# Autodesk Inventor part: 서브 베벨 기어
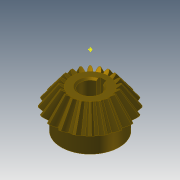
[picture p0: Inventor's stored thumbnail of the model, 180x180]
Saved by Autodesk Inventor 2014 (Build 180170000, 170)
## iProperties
Created: 2014-10
Part Number: 서브 베벨 기어
Material: Steel, Mild
Document SubType Name: Modeling
Designer: KYOUNG IL JANG
Categories: <?xml version="1.0" encoding="UTF-16"?> <MemberInstance><Categories><FamilyTemplate><FamilyTemplateParameter ValueType="xs:double" Id="1" ObjectReferenceKey="da
Mass: 134.866 g
Surface Area: 63.6518 cm^2
Volume: 17.1585 cm^3
Density: 7.86 g/cm^3
Appearance: 얼룩무늬
CustomPartVersion: 1
Company: 한국ATC센터
Author: KYOUNG IL JANG
Revision Number: 1
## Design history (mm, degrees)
node "맨 위 점"
node "메쉬 평면2"
sketch "톱니 본체 스케치"
  geometry: L1 (0, 0)-(18.003, -31.331); L2 (18.003, -31.331)-(21.664, -28.891); L3 (21.664, -28.891)-(0, 0); L4 (20, -30)-(0, 0); L5 (10.813, -18.818)-(13.012, -17.352); L6 (18.003, -31.331)-(10.813, -18.818); L7 (21.664, -28.891)-(13.012, -17.352); L8 (0, -39.387)-(0, 6.564) reference; L9 (0, -30)-(21.664, -30)
  constraints: 16 end point, 4 point on line, 3 perpendicular, 2 collinear, 1 horizontal alignment, 1 vertical alignment
  dimensions: "d0" = 40 diameter of L4.start L8 (= da_de); "d1" = 36.00616 diameter of L1.end L8 (= da_dfe); "d2" = 43.3282 diameter of L2.end L8 (= da_dae); "d3" = 14.4 distance between parallel lines of L2 L5 (= da_b); "d4" = 28.8906 vertical distance of L2.end L1.start (= da_ve)
revolve "톱니 본체" sketch "톱니 본체 스케치" stored, may be unused: angle "d5" = 90 deg
node "시작점"
node "톱니 평면"
sketch "시작 스케치"
  geometry: L1 (0, -23.505)-(0, 10.645) reference; L2 (-0.834, -2.928)-(0.834, -2.928); A1 r 8.898 centre (-9.698, -3.713) between (-0.834, -2.928) and (-3.903, 3.04); A2 r 8.898 centre (9.698, -3.713) between (3.903, 3.04) and (0.834, -2.928); A3 r 27.357 centre (0, -24.037) between (3.903, 3.04) and (-3.903, 3.04); 1 further point
  constraints: 6 point on circle, 3 centre point, 3 symmetric about line, 2 end point, 1 coincident, 1 perpendicular, 1 other
  dimensions: "d7" = 8.89846 radius of A1 (= fd_rr); "d8" = 9.69794 horizontal distance of point (0, -24.037) A1.centre (= fd_x); "d9" = 20.32439 vertical distance of point (0, -24.037) A1.centre (= fd_y); "d57" = 27.35701 radius of A3 (= 0.5 x fd_dva + 0.3 x da_he); "d58" = 21.10901 distance from line of A3.centre L2 (= 0.5 x fd_dva - 1.12 x da_he)
node "끝점"
  node "끝 평면"
sketch "3D 스케치 오른쪽"
  node "Helical Curve Right" dims "d65" = 229.90621 (computed from da_dm, da_delta, da_beta), "d66" = 31.5, "d67" = 40 (= da_de), "d68" = -5.88003 (= -da_delta), "d69" = 12.16458 (computed from fd_loft, da_delta)
node "끝 평면 오른쪽"
sketch "끝 스케치 오른쪽"
  geometry: L1 (0, -22.649)-(0, 12.15) reference; L2 (-0.497, -1.72)-(0.497, -1.72); A1 r 5.299 centre (-5.775, -2.187) between (-0.497, -1.72) and (-2.324, 1.834); A2 r 5.299 centre (5.775, -2.187) between (2.324, 1.834) and (0.497, -1.72); A3 r 16.291 centre (0, -14.29) between (2.324, 1.834) and (-2.324, 1.834); 1 further point
  constraints: 6 point on circle, 3 centre point, 3 symmetric about line, 2 end point, 1 coincident, 1 perpendicular, 1 other
  dimensions: "d70" = 5.77526 horizontal distance of A3.centre A1.centre (computed from fd_x, fd_ratio); "d71" = 12.10346 vertical distance of point (0, -14.29) A1.centre (computed from fd_y, fd_ratio); "d72" = 5.29916 radius of A1 (computed from fd_rr, fd_ratio); "d73" = 12.57071 distance from line of point (0, -14.29) L2 (computed from d58, fd_ratio); "d74" = 16.29149 radius of A3 (computed from d57, fd_ratio)
feature "로프트 오른쪽" sketch "끝 스케치 오른쪽" dims "d75" = 0, "d77" = 0, "d79" = 0, "d80" = 90 deg, "d85" = 20, "d92" = 90 deg, "d93" = 90 deg, "da_teethtype" = 0 [user parameter]
sketch "3D 스케치 왼쪽"
  node "Helical Curve Left" dims "d26" = 229.90621 (computed from da_dm, da_delta, da_beta), "d27" = 12.16458 (computed from fd_loft, da_delta), "d28" = 40 (= da_de), "d29" = -5.88003 (= -da_delta)
node "끝 평면 왼쪽"
sketch "끝 스케치 왼쪽" dims "d56" = 10.82768 (derived)
  geometry: L1 (0, -35.087)-(0, 18.089) reference; L2 (-0.497, -1.716)-(0.497, -1.716); A1 r 5.299 centre (-5.775, -2.183) between (-0.497, -1.716) and (-2.324, 1.838); A2 r 5.299 centre (5.775, -2.183) between (2.324, 1.838) and (0.497, -1.716); A3 r 16.291 centre (0, -14.287) between (2.324, 1.838) and (-2.324, 1.838); 2 further points; 1 other entity
  constraints: 6 point on circle, 3 centre point, 3 symmetric about line, 2 end point, 1 coincident, 2 other
  dimensions: "d30" = 5.29916 radius of A1 (computed from fd_rr, fd_ratio); "d31" = 5.77526 horizontal distance of point (0, -14.287) A1.centre (computed from fd_x, fd_ratio); "d32" = 12.10346 vertical distance of A1.centre point (0, -14.287) (computed from fd_y, fd_ratio); "d61" = 16.29149 radius of A3 (computed from d57, fd_ratio); "d62" = 12.57071 distance from line of point (0, -14.287) L2 (computed from d58, fd_ratio)
feature "로프트 왼쪽" sketch "끝 스케치 왼쪽" dims "d35" = 0, "d37" = 0, "d39" = 0, "d40" = 90 deg, "d84" = 10, "d90" = 90 deg, "d91" = 90 deg, "da_teethtype" = 0 [user parameter]
sketch "본체 스케치"
  geometry: L1 (0, -35.038)-(0, -19.531) reference; L2 (18.003, -31.331)-(10.813, -18.818) reference; L3 (10.813, -18.818)-(0, -18.818); L4 (18.003, -31.331)-(0, -31.331)
  constraints: 4 end point, 2 perpendicular, 2 point on line
revolve "본체 고정" sketch "본체 스케치" stored, may be unused: angle "d46" = 90 deg
feature "피치 지름" dims angle "d47" = 90 deg
sketch "스케치8"
  geometry: C1 r 17 at (0, 0); 1 further point
  constraints: 1 centre point, 1 coincident
  dimensions: "d94" = 34 diameter of C1
extrude "돌출1" join sketch "스케치8" distance "d95" = 10; taper "d96" = 0 deg
sketch "스케치9"
  geometry: 1 further point
hole "구멍1" sketch "스케치9" at (0, 0) diameter "d97" = 12; stored, may be unused: countersink angle "d101" = 90 deg, drill point angle "d103" = 118 deg; dims "d98" = 6, "d99" = 4, "d100" = 2, "d102" = 8
sketch "스케치10"
  geometry: 1 further point
sketch "스케치11"
  geometry: 1 further point
sketch "스케치12"
  geometry: L1 (-2, 5.657)-(-2, 7.8); L2 (-2, 7.8)-(2, 7.8); L3 (2, 7.8)-(2, 5.657); A1 r 6 centre (0, 0) between (-2, 5.657) and (2, 5.657) reference; 1 further point
  constraints: 6 end point, 2 parallel, 2 point on circle, 1 perpendicular, 1 vertical
  dimensions: "d104" = 4 distance of L1.end L2.end; "d105" = 13.8 dimension on A1 L2
extrude "돌출2" cut sketch "스케치12" stored distance "d106" = 7; taper "d107" = 0 deg
chamfer "모따기1" distance "d108" = 1; stored, may be unused: second distance "d109" = 2, angle "d110" = 45 deg
body "Solid1"
feature "로프트" dims "d17" = 0, "d18" = 90 deg, "d19" = 0, "d20" = 90 deg, "d89" = 0, "da_teethtype" = 0 [user parameter]
pattern_circular "원형 패턴" dims angle "d22" = 360 deg, "d88" = 0, "da_teethtype" = 0 [user parameter]
pattern_circular "원형 패턴 오른쪽" dims angle "d82" = 360 deg, "da_teethtype" = 0 [user parameter]
pattern_circular "원형 패턴 왼쪽" dims angle "d42" = 360 deg, "da_teethtype" = 0 [user parameter]
sketch "끝 스케치"
  geometry: L1 (0, -15.359)-(0, 6.983) reference; L2 (-0.497, -1.72)-(0.497, -1.72); A1 r 5.299 centre (-5.775, -2.187) between (-0.497, -1.72) and (-2.324, 1.834); A2 r 5.299 centre (5.775, -2.187) between (2.324, 1.834) and (0.497, -1.72); A3 r 16.291 centre (0, -14.29) between (2.324, 1.834) and (-2.324, 1.834); 1 further point
  constraints: 6 point on circle, 3 centre point, 3 symmetric about line, 2 end point, 1 coincident, 1 other
  dimensions: "d12" = 5.29916 radius of A1 (computed from fd_rr, fd_ratio); "d15" = 5.77526 horizontal distance of A1.centre point (0, -14.29) (computed from fd_x, fd_ratio); "d16" = 12.10346 vertical distance of A1.centre point (0, -14.29) (computed from fd_y, fd_ratio); "d59" = 16.29149 radius of A3 (computed from d57, fd_ratio); "d60" = 12.57071 distance from line of A3.centre L2 (computed from d58, fd_ratio)
sketch "Sketch6"
  geometry: L1 (20, -30)-(0, 0) reference; L2 (0, -37.8)-(0, 6.3) reference
body "Srf1"
other parameters: "da_b" = 14.4 [user parameter; used in 2 equation terms], "da_de" = 40 [user parameter; used in 4 equation terms], "da_dae" = 43.3282 [user parameter; used in 2 equation terms], "da_dfe" = 36.00616 [user parameter; used in 1 equation term], "da_le" = 36.05551 [user parameter; used in 1 equation term], "da_omega" = 90 deg [user parameter; used in 1 equation term], "da_beta" = 0 [user parameter; used in 2 equation terms], "da_delta" = 5.88003 [user parameter; used in 8 equation terms], "da_alpha" = 20 deg [user parameter; used in 2 equation terms], "da_he" = 4.4 [user parameter; used in 4 equation terms], "da_ve" = 28.8906 [user parameter; used in 1 equation term], "fd_dv" = 48.07402 (computed from da_de, da_delta) [user parameter; used in 1 equation term], "fd_dva" = 52.07402 (computed from da_dae, da_delta) [user parameter; used in 3 equation terms], "fd_dvb" = 45.1748 (computed from fd_dv, da_alpha) [user parameter; used in 2 equation terms], "da_zv" = 240.37008 [user parameter; used in 1 equation term], "fd_loft" = 14.62 (= da_b + 0.05 x da_he) [user parameter; used in 4 equation terms], "fd_ratio" = 5.95514 (computed from da_le, fd_loft) [user parameter; used in 15 equation terms], "fd_rr" = 8.89846 (computed from fd_dd, fd_dvb) [user parameter; used in 6 equation terms], "fd_angle" = 0.66075 (computed from da_zv) [user parameter; used in 4 equation terms], "fd_x1" = 1.58709 (computed from da_dvw, fd_angle) [user parameter; used in 1 equation term], "fd_y1" = 23.98456 (computed from da_dvw, fd_angle) [user parameter; used in 1 equation term], "fd_x2" = 8.11084 (computed from fd_rr, fd_angle2, fd_angle) [user parameter; used in 1 equation term], "fd_y2" = 3.66016 (computed from fd_rr, fd_angle2, fd_angle) [user parameter; used in 1 equation term], "fd_x" = 9.69794 (= fd_x1 + fd_x2) [user parameter; used in 4 equation terms], "fd_y" = 20.32439 (= fd_y1 - fd_y2) [user parameter; used in 4 equation terms], "fd_angle2" = 3.57832 (computed from fd_dvb, fd_dd, da_alpha) [user parameter; used in 2 equation terms], "fd_dd" = 48.55402 (= fd_dva - 0.8 x da_he) [user parameter; used in 2 equation terms], "da_dvw" = 48.07402 [user parameter; used in 2 equation terms], "d11" = 14.62 (= fd_loft), "da_dm" = 32.01232 [user parameter; used in 2 equation terms], "da_x" = 0 [user parameter], "da_m" = 2 [user parameter], "d48" = 0, "d49" = 0, "d50" = 90 deg (= da_omega), "d51" = 9 deg (computed from da_z), "d52" = 0, "d53" = 0, "d54" = 0
